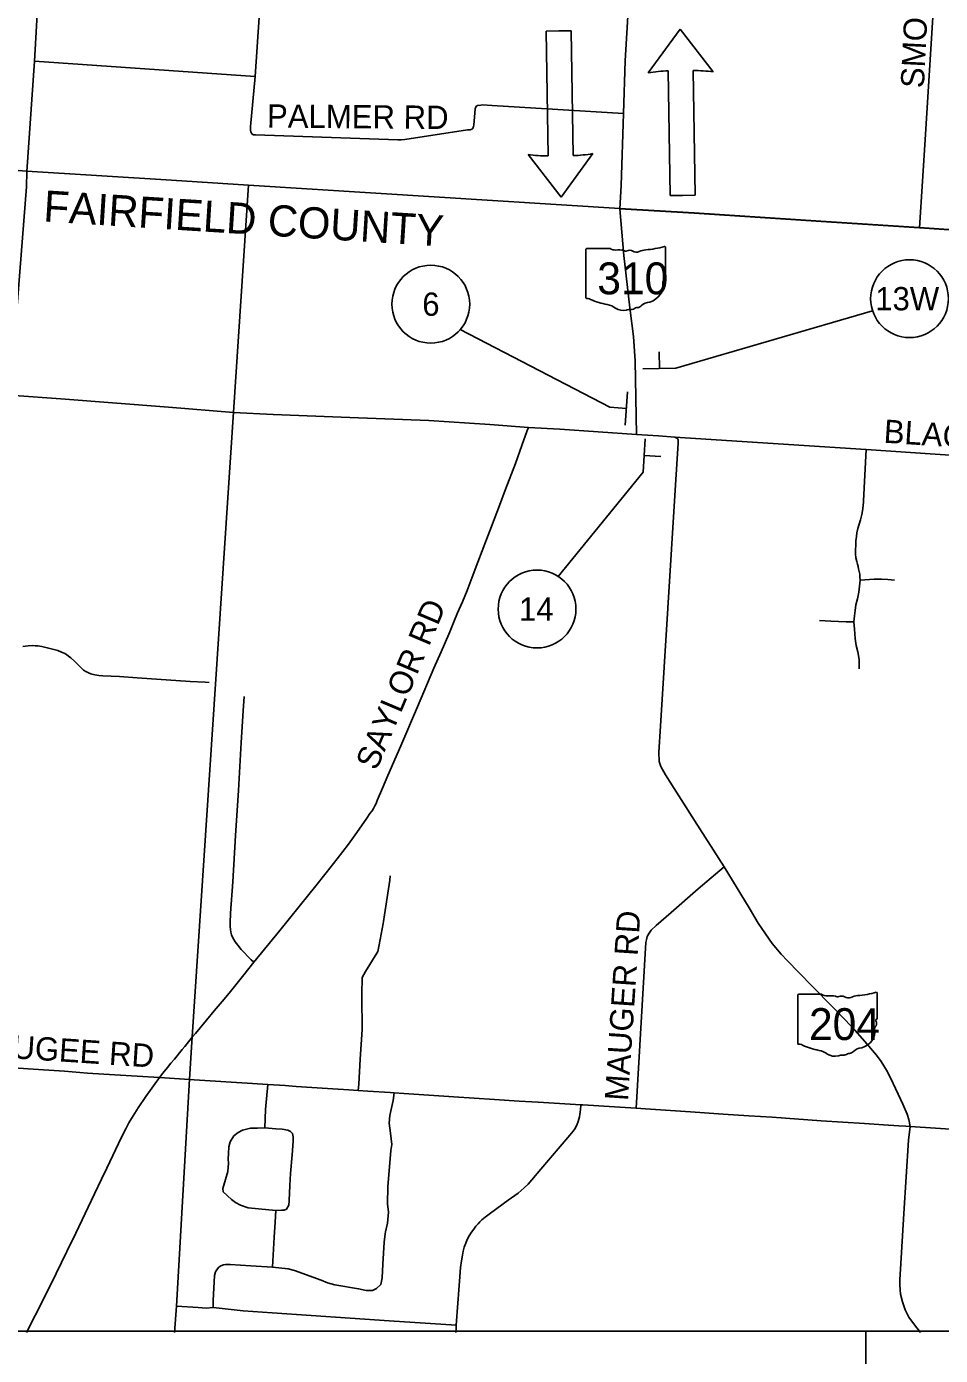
# Model space of a CAD drawing. Extents: x 1880545 to 1948545, y 79309 to 723051.
# Drawn here: x 1910544 to 1921540, y 690858 to 706837 of the extents above; entities that cross this region are included whole.
import ezdxf

# ---------------------------------------------------------------- set-up
doc = ezdxf.new("R2010")
doc.units = 0
for name, color, linetype in [('GM_X_County', 7, 'Continuous'), ('GM_X_County_Road', 7, 'Continuous'), ('GM_X_County_Text', 7, 'Continuous'), ('GM_X_State_Route', 7, 'Continuous'), ('GM_X_State_Shield', 7, 'Continuous'), ('GM_X_Township', 7, 'Continuous'), ('GM_X_Township_Road', 7, 'Continuous'), ('SH_Text', 7, 'Continuous')]:
    doc.layers.add(name, color=color, linetype=linetype)

msp = doc.modelspace()

# ---------------------------------------------------------------- linework, layer by layer
at = {"layer": 'GM_X_County'}
msp.add_lwpolyline([(1889272, 706620), (1891302, 706476), (1891974, 706453), (1893110, 706354), (1893307, 706337), (1894183, 706297), (1895332, 706215), (1898403, 705973), (1899947, 705888), (1900524, 705848), (1900988, 705813), (1901285, 705794), (1903803, 705612), (1907401, 705337), (1908910, 705222), (1910548, 705097), (1912287, 704990), (1913213, 704931), (1917683, 704648), (1918575, 704596), (1920102, 704498), (1921285, 704420), (1922414, 704344)], dxfattribs=at)
at = {"layer": 'GM_X_County_Road'}
for points in [[(1918344, 701901), (1920647, 701753), (1922902, 701601), (1923097, 701588), (1923778, 701542), (1924079, 701522), (1925008, 701454), (1925058, 701452), (1925112, 701448), (1926417, 701359), (1926469, 701355), (1926521, 701352), (1927717, 701271), (1927760, 701268), (1927820, 701264), (1928206, 701237)], [(1903729, 694782), (1903909, 694770), (1908084, 694476), (1908354, 694456), (1908506, 694450), (1908895, 694421), (1909204, 694398), (1909837, 694354), (1909874, 694351), (1910152, 694333), (1910625, 694301), (1911001, 694277), (1911279, 694254), (1911606, 694232), (1912143, 694200)], [(1912143, 694200), (1912504, 694177), (1912562, 694174)], [(1912562, 694174), (1913263, 694130), (1913448, 694118), (1913655, 694104), (1913786, 694094), (1914163, 694068), (1914420, 694052), (1914535, 694045), (1914649, 694037), (1914918, 694020), (1914966, 694017), (1915083, 694009), (1915684, 693968), (1916175, 693935), (1916470, 693917), (1916699, 693905), (1917212, 693872), (1917239, 693871), (1917681, 693842), (1917877, 693830), (1917992, 693822), (1918532, 693786), (1918927, 693760), (1919236, 693741), (1919514, 693723), (1920103, 693680), (1920627, 693647), (1920854, 693631), (1921041, 693618), (1921125, 693615), (1921174, 693612)], [(1915707, 691136), (1915711, 691191), (1915713, 691223), (1915752, 691752), (1915767, 691916), (1915777, 691997), (1915788, 692062), (1915799, 692114), (1915811, 692159), (1915828, 692207), (1915847, 692251), (1915870, 692295), (1915896, 692339), (1915924, 692378), (1915951, 692413), (1915976, 692442), (1915999, 692465), (1916023, 692488), (1916061, 692520), (1916126, 692570), (1916339, 692724), (1916459, 692810), (1916497, 692840), (1916533, 692873), (1916579, 692919), (1916622, 692968), (1916731, 693098), (1917081, 693505), (1917121, 693556), (1917140, 693582), (1917156, 693610), (1917170, 693639), (1917181, 693670), (1917190, 693701), (1917196, 693729), (1917201, 693758), (1917204, 693781), (1917207, 693820), (1917211, 693861), (1917212, 693872)]]:
    msp.add_lwpolyline(points, dxfattribs=at)
at = {"layer": 'GM_X_State_Route'}
for points in [[(1917725, 705792), (1917745, 706424), (1917797, 707299), (1917797, 707469), (1917775, 707653), (1917577, 708419), (1917568, 708450)], [(1917684, 704645), (1917698, 704926), (1917725, 705792)], [(1917882, 701932), (1917868, 702816), (1917846, 703109), (1917804, 703456), (1917729, 704085), (1917684, 704645)], [(1910399, 702402), (1910958, 702359), (1912250, 702260), (1913034, 702198), (1913513, 702172), (1914434, 702137), (1915385, 702102), (1916119, 702054), (1916582, 702017), (1916959, 701997), (1917882, 701932)], [(1917882, 701932), (1918148, 701915), (1918344, 701901), (1918376, 701884), (1918381, 701876), (1918383, 701867), (1918384, 701848), (1918384, 701828), (1918346, 701263), (1918170, 698425), (1918153, 698114), (1918155, 697998), (1918177, 697939), (1918232, 697838), (1918582, 697290), (1918936, 696733)], [(1918936, 696733), (1919239, 696239), (1919347, 696058), (1919514, 695811), (1919623, 695682), (1919698, 695602), (1919834, 695464), (1920003, 695289), (1920236, 695055), (1920481, 694802), (1920632, 694635), (1920771, 694468), (1920828, 694393), (1920890, 694288), (1920942, 694188), (1921086, 693878), (1921140, 693759), (1921161, 693697), (1921174, 693612)], [(1921174, 693612), (1921784, 693573), (1922832, 693507), (1923267, 693480), (1923569, 693461), (1923801, 693461), (1926597, 693281), (1927949, 693195), (1928206, 693179)]]:
    msp.add_lwpolyline(points, dxfattribs=at)
at = {"layer": 'GM_X_State_Shield'}
for p, q in [((1917564, 704168), (1917284, 704168)), ((1918231, 703878), (1918231, 704182)), ((1917274, 704158), (1917274, 703577)), ((1918231, 703879), (1918231, 703878)), ((1919823, 695191), (1919823, 694610)), ((1920112, 695201), (1919832, 695201)), ((1920780, 694911), (1920780, 695215)), ((1920780, 694911), (1920780, 694911))]:
    msp.add_line(p, q, dxfattribs=at)
for centre, major_axis, start_param, end_param in [((1917285, 704159), (11.1, 0), 1.712693, 3.28349), ((1917631, 704236), (108, 0), 4.042523, 4.731795), ((1917890, 704960), (1015, 0), 4.814394, 5.042369), ((1918221, 704184), (10.7, 0), 6.141152, 7.989035), ((1917666, 703842), (386, 0), 1.404758, 1.657858), ((1917754, 704162), (31, 0), 3.836095, 5.185415), ((1917800, 704095), (64.5, 0), 0.950623, 2.079405), ((1917883, 704187), (77.6, 0), 4.081561, 5.145723), ((1918020, 703991), (204, 0), 1.699011, 2.107814), ((1918229, 703856), (16.5, 0), 1.883978, 3.671073), ((1918124, 703818), (99, 0), 5.934695, 6.695948), ((1918220, 703877), (11.4, 0), 5.05454, 6.418171), ((1917947, 703713), (254, 0), 5.101752, 6.440018), ((1918270, 703751), (72, 0), 2.387724, 3.262537), ((1917285, 703576), (11.2, 0), 3.00124, 4.508301), ((1917287, 703635), (85.4, 0), 4.665946, 4.897461), ((1917304, 703543), (30.8, 0), 0.519207, 1.627899), ((1917693, 704066), (733, 0), 4.195997, 4.488961), ((1917475, 703316), (229, 0), 0.823519, 1.323587), ((1917723, 703540), (146, 0), 4.026481, 4.996735), ((1917807, 703340), (120, 0), 1.495662, 1.94098), ((1917817, 703497), (77.5, 0), 4.691044, 5.507374), ((1917887, 703441), (21.8, 0), 1.147584, 2.315152), ((1917878, 703521), (82, 0), 4.937069, 5.64225), ((1918054, 703414), (139, 0), 1.647645, 2.488434), ((1920439, 695993), (1015, 0), 4.814394, 5.042369), ((1920769, 695216), (10.7, 0), 6.141152, 7.989035), ((1919833, 695192), (11.1, 0), 1.712693, 3.28349), ((1920179, 695268), (108, 0), 4.042523, 4.731795), ((1920215, 694875), (386, 0), 1.404758, 1.657858), ((1920302, 695195), (31, 0), 3.836095, 5.185415), ((1920348, 695128), (64.5, 0), 0.950623, 2.079405), ((1920431, 695220), (77.6, 0), 4.081561, 5.145723), ((1920568, 695023), (204, 0), 1.699011, 2.107814), ((1920777, 694889), (16.5, 0), 1.883978, 3.671073), ((1920768, 694910), (11.4, 0), 5.05454, 6.418171), ((1920496, 694745), (254, 0), 5.101752, 6.440018), ((1920818, 694784), (72, 0), 2.387724, 3.262537), ((1920672, 694850), (99, 0), 5.934695, 6.695948), ((1919834, 694608), (11.2, 0), 3.00124, 4.508301), ((1919835, 694668), (85.4, 0), 4.665946, 4.897461), ((1919853, 694576), (30.8, 0), 0.519207, 1.627899), ((1920241, 695098), (733, 0), 4.195997, 4.488961), ((1920023, 694349), (229, 0), 0.823519, 1.323587), ((1920271, 694573), (146, 0), 4.026481, 4.996735), ((1920355, 694372), (120, 0), 1.495662, 1.94098), ((1920366, 694530), (77.5, 0), 4.691044, 5.507374), ((1920436, 694473), (21.8, 0), 1.147584, 2.315152), ((1920426, 694553), (82, 0), 4.937069, 5.64225), ((1920603, 694446), (139, 0), 1.647645, 2.488434)]:
    msp.add_ellipse(centre, major_axis=major_axis, ratio=0.8, start_param=start_param, end_param=end_param, dxfattribs=at)
at = {"layer": 'GM_X_Township'}
for points in [[(1922414, 704344), (1921285, 704420), (1920102, 704498), (1918575, 704596), (1917683, 704648), (1913213, 704931), (1912287, 704990), (1910548, 705097), (1908910, 705222), (1907401, 705337), (1903803, 705612), (1901285, 705794), (1900988, 705813), (1900524, 705848), (1899947, 705888), (1898403, 705973), (1895332, 706215), (1894183, 706297), (1893307, 706337), (1893110, 706354), (1891974, 706453), (1891302, 706476), (1889272, 706620), (1889456, 709272)], [(1901285, 705794), (1903803, 705612), (1907401, 705337), (1908910, 705222), (1910548, 705097), (1912287, 704990), (1913213, 704931), (1913032, 702200), (1912537, 694689), (1912503, 694180), (1912347, 691452), (1912324, 691136)], [(1912324, 691136), (1912347, 691452), (1912503, 694180), (1912537, 694689), (1913032, 702200), (1913213, 704931), (1917683, 704648), (1918575, 704596), (1920102, 704498), (1921285, 704420), (1922414, 704344), (1926703, 704052), (1928206, 703952)]]:
    msp.add_lwpolyline(points, dxfattribs=at)
at = {"layer": 'GM_X_Township_Road'}
for p, q in [((1910713, 707744), (1910640, 706422)), ((1910640, 706422), (1910549, 705095)), ((1920615, 701136), (1920647, 701753))]:
    msp.add_line(p, q, dxfattribs=at)
for points in [[(1913294, 706235), (1913472, 708857), (1913537, 709895)], [(1921286, 704417), (1921359, 705539), (1921461, 707147), (1921556, 708597)], [(1910640, 706422), (1913294, 706235), (1913237, 705637), (1913238, 705592), (1913244, 705572), (1913250, 705554), (1913260, 705544), (1913276, 705536), (1913298, 705537), (1915010, 705476), (1915052, 705474), (1915094, 705478), (1915849, 705594), (1915881, 705596), (1915903, 705602), (1915913, 705612), (1915923, 705634), (1915925, 705652), (1915942, 705849), (1915948, 705867), (1915954, 705879), (1915964, 705885), (1915972, 705891), (1915990, 705889), (1916030, 705895), (1916145, 705889), (1917725, 705792)], [(1917725, 705792), (1917698, 704926), (1917684, 704645)], [(1910347, 702406), (1910544, 704909), (1910549, 705095)], [(1917684, 704645), (1918577, 704593), (1920103, 704495), (1921286, 704417)], [(1921286, 704417), (1922415, 704341), (1926704, 704049)], [(1916582, 702017), (1916569, 701978), (1916503, 701799), (1916425, 701584), (1916303, 701263), (1916233, 701077), (1916137, 700827), (1916078, 700671), (1915973, 700395), (1915907, 700218), (1915844, 700056), (1915790, 699921), (1915731, 699786), (1915686, 699681), (1915636, 699560), (1915571, 699409), (1915531, 699320), (1915446, 699124), (1915246, 698657), (1915047, 698190), (1914890, 697830), (1914826, 697679), (1914764, 697530), (1914749, 697493), (1914736, 697465), (1914720, 697435), (1914702, 697408), (1914676, 697373), (1914640, 697318), (1914516, 697147), (1914416, 697005), (1914282, 696828), (1914149, 696662), (1914009, 696485), (1913940, 696399), (1913593, 695968), (1913278, 695587), (1913159, 695433), (1912983, 695216), (1912897, 695115), (1912803, 695003), (1912707, 694891), (1912575, 694731)], [(1920561, 699115), (1920561, 699227), (1920546, 699319), (1920527, 699395), (1920513, 699480), (1920505, 699592), (1920498, 699680), (1920505, 699751), (1920513, 699815), (1920523, 699882), (1920540, 699957), (1920558, 700037), (1920564, 700107), (1920573, 700182), (1920569, 700218), (1920568, 700253), (1920562, 700285), (1920555, 700317), (1920550, 700343), (1920540, 700371), (1920532, 700406), (1920523, 700450), (1920516, 700496), (1920517, 700546), (1920521, 700600), (1920522, 700654), (1920528, 700707), (1920535, 700749), (1920547, 700802), (1920563, 700855), (1920578, 700905), (1920594, 700969), (1920606, 701040), (1920611, 701084), (1920614, 701120), (1920615, 701136)], [(1920573, 700182), (1920742, 700191), (1920830, 700191), (1920908, 700187), (1920987, 700182)], [(1920083, 699697), (1920219, 699689), (1920406, 699681), (1920498, 699680)], [(1910499, 699384), (1910564, 699391), (1910613, 699393), (1910646, 699392), (1910679, 699389), (1910727, 699382), (1910792, 699368), (1910856, 699352), (1910919, 699333), (1910965, 699316), (1910995, 699302), (1911023, 699286), (1911050, 699268), (1911076, 699247), (1911124, 699202), (1911206, 699121), (1911231, 699100), (1911258, 699082), (1911288, 699067), (1911318, 699054), (1911333, 699049), (1911366, 699042), (1911414, 699036), (1911463, 699031), (1911661, 699020), (1911874, 699005), (1912513, 698963), (1912694, 698952), (1912743, 698948)], [(1913278, 695587), (1913248, 695614), (1913128, 695741), (1913085, 695790), (1913055, 695830), (1913038, 695858), (1913023, 695887), (1913011, 695917), (1913002, 695949), (1912996, 695981), (1912993, 696014), (1912994, 696062), (1912999, 696177), (1913025, 696553), (1913057, 697110), (1913092, 697650), (1913126, 698228), (1913149, 698610), (1913161, 698782)], [(1917877, 693830), (1917996, 695825), (1918002, 695857), (1918013, 695894), (1918034, 695937), (1918061, 695973), (1918118, 696027), (1918298, 696183), (1918625, 696467), (1918936, 696733)], [(1914535, 694045), (1914542, 694119), (1914559, 694419), (1914581, 694777), (1914577, 695169), (1914578, 695224), (1914580, 695381), (1914580, 695404), (1914623, 695473), (1914760, 695697), (1914771, 695715), (1914786, 695797), (1914835, 696054), (1914839, 696076), (1914851, 696158), (1914913, 696572), (1914920, 696624)], [(1912575, 694731), (1912538, 694686), (1912447, 694574), (1912415, 694537), (1912324, 694421), (1912281, 694372), (1912239, 694321), (1912183, 694252), (1912143, 694200)], [(1912143, 694200), (1911979, 693971), (1911888, 693836), (1911826, 693739), (1911776, 693655), (1911737, 693583), (1911686, 693481), (1911508, 693112), (1911445, 692979), (1911363, 692801), (1911135, 692329), (1911029, 692108), (1910901, 691843), (1910755, 691550), (1910544, 691136)], [(1913503, 691921), (1913523, 692280), (1913534, 692461), (1913543, 692603), (1913212, 692635), (1913119, 692664), (1913059, 692699), (1913010, 692733), (1912909, 692826), (1912906, 692867), (1912939, 692975), (1912964, 693069), (1912972, 693172), (1912968, 693219), (1912973, 693286), (1912977, 693367), (1912995, 693428), (1913037, 693497), (1913091, 693537), (1913142, 693567), (1913191, 693581), (1913239, 693590), (1913324, 693592), (1913409, 693596), (1913419, 693815), (1913448, 694118)], [(1914863, 692343), (1914885, 692448), (1914897, 692580), (1914885, 692680), (1914890, 692886), (1914925, 693322), (1914940, 693395), (1914922, 693531), (1914906, 693652), (1914914, 693743), (1914956, 693923), (1914966, 694017)], [(1913543, 692603), (1913612, 692605), (1913643, 692607), (1913671, 692617), (1913700, 692665), (1913704, 692722), (1913713, 692901), (1913719, 693044), (1913738, 693271), (1913751, 693436), (1913753, 693486), (1913745, 693526), (1913720, 693552), (1913686, 693568), (1913621, 693578), (1913543, 693582), (1913409, 693596)], [(1921299, 691136), (1921226, 691228), (1921159, 691320), (1921115, 691408), (1921082, 691501), (1921061, 691597), (1921051, 691702), (1921052, 691773), (1921058, 691896), (1921099, 692563), (1921157, 693445), (1921174, 693612)], [(1912788, 691433), (1912788, 691520), (1912804, 691821), (1912818, 691864), (1912840, 691898), (1912859, 691920), (1912881, 691935), (1912915, 691947), (1912941, 691952), (1912992, 691952), (1913242, 691934), (1913503, 691921), (1913690, 691901), (1913769, 691881), (1914089, 691762), (1914164, 691732), (1914255, 691706), (1914539, 691660), (1914632, 691639), (1914706, 691638), (1914756, 691662), (1914805, 691711), (1914824, 691793), (1914829, 691955), (1914847, 692221), (1914859, 692322), (1914863, 692343)], [(1915713, 691223), (1914908, 691274), (1913499, 691372), (1913150, 691394), (1912788, 691433), (1912705, 691428), (1912610, 691435), (1912348, 691450)]]:
    msp.add_lwpolyline(points, dxfattribs=at)
at = {"layer": 'SH_Text'}
for p, q in [((1916797, 706782), (1916947, 706784)), ((1916819, 705282), (1916797, 706782)), ((1916947, 706784), (1917097, 706786)), ((1917097, 706786), (1917119, 705287)), ((1918025, 706281), (1918407, 706806)), ((1918407, 706806), (1918805, 706292)), ((1918287, 704804), (1918265, 706304)), ((1918564, 706308), (1918587, 704808)), ((1916976, 704784), (1916578, 705298)), ((1917359, 705309), (1916976, 704784)), ((1918437, 704806), (1918287, 704804)), ((1918587, 704808), (1918437, 704806)), ((1918358, 702729), (1920724, 703419)), ((1915762, 703194), (1917562, 702259)), ((1918158, 702726), (1918155, 702926)), ((1917958, 702722), (1918358, 702729)), ((1917747, 702046), (1917775, 702445)), ((1917761, 702245), (1917562, 702259)), ((1917987, 701879), (1917963, 701480)), ((1917975, 701679), (1918175, 701667)), ((1917963, 701480), (1916940, 700226)), ((1920641, 691152), (1920641, 687581))]:
    msp.add_line(p, q, dxfattribs=at)
msp.add_lwpolyline([(1884490, 720381), (1928141, 720381), (1928141, 691152), (1884490, 691152)], close=True, dxfattribs=at)
for centre in [(1921168, 703565), (1915408, 703499), (1916686, 699833)]:
    msp.add_circle(centre, 468, dxfattribs=at)
for centre, start, end in [((1918287, 704804), 90.8443, 100.0609), ((1918587, 704808), 81.6277, 90.8443), ((1916797, 706782), 261.6277, 270.8443), ((1917097, 706786), 270.8443, 280.0609)]:
    msp.add_arc(centre, 1500, start, end, dxfattribs=at)

# ---------------------------------------------------------------- texts
at = {"layer": 'GM_X_County_Text'}
msp.add_text('FAIRFIELD COUNTY', height=375, rotation=356.3996, dxfattribs=at).set_placement((1910740, 704494))
at = {"layer": 'GM_X_State_Shield'}
for s, p in [('310', (1917411, 703618)), ('204', (1919958, 694651))]:
    msp.add_text(s, height=382.9, dxfattribs=at).set_placement(p)
at = {"layer": 'SH_Text'}
for s, rotation, p in [('SMOKE RD', 87.1395, (1921340, 706092)), ('PALMER RD', 359.5442, (1913436, 705622)), ('BLACKLICK RD', 356.2172, (1920851, 701834)), ('SAYLOR RD', 67.0991, (1914754, 697880)), ('MAUGER RD', 86.2, (1917780, 693914)), ('REFUGEE RD', 356.2172, (1909620, 694481))]:
    msp.add_text(s, height=280, rotation=rotation, dxfattribs=at).set_placement(p)
for s, p in [('13W', (1920755, 703425)), ('6', (1915305, 703359)), ('14', (1916469, 699693))]:
    msp.add_text(s, height=280, dxfattribs=at).set_placement(p)

doc.saveas('drawing.dxf')
